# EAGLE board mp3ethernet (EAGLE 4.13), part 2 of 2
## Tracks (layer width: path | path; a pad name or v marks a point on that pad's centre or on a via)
+3V3  (via drill 0.5, 0.6)
  Top 0.254: 44.02,20 v43.97,19.94 v43.96,19.94 43.84,19.83 40.2,19.83 39.92,19.91 C73.1 | 43.2,60.31 | 43.2,60.31 43.27,60.29 43.83,60.84 v45.42,60.83 | R30.2 15.19,2.84 | L5.2 22.22,2.94 22.18,2.9 | 26.39,14.46 v26.39,14.62 26.39,14.47 26.65,14.22 | 25.24,4.88 25.25,4.87 25.25,4.86 | IC5.23 14.84,48.72 14.82,48.74 14.82,49.28 14.31,49.53 IC5.21 13.34,49.52 12.81,48.99 12.81,48.33 | 12.81,48.33 12.81,48.14 12.2,47.53 12.2,46.86 12.17,46.83 C25.2 | 47.49,28.3 47.5,28.31 | v48.43,28.01 48.42,28.01 48.44,28.03 48.47,28.02 | C15.1 24.51,39.74 v23.1,38.33 | 21.68,31.06 21.56,31.18 21.56,31.19 CON1.4 21.56,30.9 21.57,30.9 21.02,31.45 v20.46,31.45 | C13.1 21.68,23.9 | C27.1 13.31,56.47 13.3,56.46 14.1,55.66 14.49,55.66 14.84,55.31 IC5.13 14.84,54.6 13.94,54.6 v13.92,54.59 | IC1.71 57.97,44.8 v58.12,44.96 58.39,45.23 63.92,45.23 C61.2 | IC1.48 48.13,35.76 47.64,35.27 47.64,33.91 | v13.33,48.33 12.81,48.33 | 42.8,47.31 42.79,47.31 IC1.25 | IC8.5 33.06,35.79 32.82,35.55 29.96,35.55 29.51,36.01 | 21.2,33.97 C24.1 | 21.2,33.97 21.2,31.92 22.01,31.11 22.01,31.1 | 29.51,36.01 29.56,36.06 29.58,36.06 C67.1 | 24.95,39.74 24.95,38.19 25.96,37.18 28.3,37.18 28.31,37.19 | 28.31,37.19 28.31,37.2 | 21.2,33.97 21.2,33.11 21.62,32.7 22.62,32.7 v22.75,32.82 | 40.38,29.73 43.69,29.72 v44.03,29.38 | 40.38,29.73 v36.27,29.74 | 29.51,36.01 29.49,36.01 28.31,37.19 | 47.64,33.91 v45.91,33.91 | 47.64,33.91 47.57,33.84 47.44,33.84 | 40.38,29.73 40.38,29.67 40.3,29.59 C35.1
  Top 0.305: IC1.24 42.79,47.8 | IC1.24 42.78,47.38 42.75,47.35 42.78,47.32 IC1.25 44.96,47.3 45.84,46.44 45.85,43.8 | IC1.23 IC1.24 | 45.85,43.8 IC1.32 | 15.19,2.84 16.15,1.85 21.82,1.85 22.18,2.18 22.18,2.9 | L5.2 23.16,2.99 24.81,4.58 24.97,4.58 25.25,4.86 | 26.39,14.46 26.89,13.96 26.89,5.61 26.14,4.88 25.24,4.88 | v36.19,16.36 31.89,16.36 29.75,14.22 26.65,14.22 | 21.68,31.06 C13.1 | CON1.4 21.57,31.29 21.76,31.1 22.01,31.1 v22.6,31.1 | C24.1 21.29,32.05 21.63,31.7 | 56.01,44.8 IC1.71 54.18,44.8 50.87,48.06 50.53,48.4 | 46.07,44.18 46.1,44.05 45.85,43.8 | 45.85,43.8 44.95,43.8 | 47.45,28.26 47.44,33.84 47.44,33.88 | 47.45,28.26 47.48,28.24 | 47.45,28.26 47.45,28.07 47.48,28.05 48.39,28.05 v48.43,28.01 | 47.45,28.26 47.45,22.24 45.1,19.93 44.12,19.93 44.05,20.01 43.98,19.94 v43.97,19.94 | 47.49,28.3 47.49,28.19 47.48,28.17 47.45,28.2 47.45,28.26 | v38.07,47.11 38.27,47.31 39.17,47.31 39.49,47.63 41.13,47.63 41.44,47.31 42.79,47.31 | C59.+ 22.06,44.6 21.96,44.7 21.96,48.35 v21.95,48.37 | 50.53,48.4 50.52,48.41 | 50.53,48.4 | v45.91,33.91 v45.93,33.91 46.14,33.7
  Top 0.406: C15.1 24.95,39.74 24.96,39.76 23.73,40.99 C59.+ | v51.84,48.98 51.11,48.98 50.53,48.4 48.96,46.83 48.96,44.2 v48.73,43.97 v48.73,43.99 48.54,44.18 46.07,44.18 | 25.12,4.82 25.09,4.78 | 25.12,4.82 v25.12,4.87 | 25.24,4.88 25.19,4.88 25.12,4.82
  Top 0.61: SV3.2 46.15,55.49 46.14,55.49 46.14,55.91 44.16,57.9 44.16,59.35 43.2,60.31 41.43,62.08 41.43,64 | 41.43,64 41.43,64.05 41.41,64.03 L3.P$2 38.96,64.03 38.98,64.01 39.71,64.75 | 41.43,64 41.42,64 42.18,63.24 v42.18,63.21
  Bottom 0.254: 38.28,17.62 U1.28 38.24,17.59 38.23,17.58 38.23,17.59 38.23,18.07 38.24,18.09 | U1.20 43.44,17.61 | U1.20 | 43.44,17.66 U1.20 | U1.20 43.42,17.62 | U1.20 U1.19 | 46.69,16.98 U1.15 | 43.44,17.66 U1.20 | 43.44,17.66 43.44,16.53 43.98,15.97 46.04,15.97 46.67,16.59 46.69,16.98 | 46.69,16.98 46.69,16.99 | 46.68,16.98 46.68,16.99 | 46.69,16.98 46.68,16.98 | 46.68,16.98 46.87,16.79 49.7,16.79 49.79,16.81 50.1,16.5 50.1,16.47 50.09,16.46 52.71,14.2 L6.2 52.95,14.2 | C12.1 53.77,12.24 53.96,13.03 53.96,13.2 52.95,14.2 | 43.44,19.44 43.42,19.42 | 43.96,19.93 v43.97,19.94 | v45.42,60.83 v45.43,60.82 47.12,60.81 48.67,62.36 R3.2 | R41.2 | 26.41,5.57 26.47,5.57 R41.2 | R43.2 26.48,11.08 26.53,11.13 26.38,11.28 C52.2 26.38,14.61 v26.39,14.62 | v25.12,4.87 25.12,4.91 25.14,4.92 25.09,4.97 | IC2.14 19.53,36.07 19.51,36.05 19.49,36.07 IC2.13 19.48,37.31 18.57,38.22 C56.1 | v48.43,28.01 48.42,28.01 48.4,28.02 47.29,28.02 R11.2 47.16,27.85 47.17,27.84 47.2,27.87 47.2,28.5 46.32,29.38 v44.03,29.38 | v36.19,16.36 36.15,16.39 | 61.69,41.65 61.7,41.64 | 61.69,41.65 R40.2 62.63,41.65 62.96,41.32 62.97,37.86 62.56,37.46 62.56,37.17 62.55,37.15 IC10.8 | 61.69,41.65 61.66,41.67 R39.2 59.33,41.76 59.34,41.78 58.13,42.98 v58.12,44.96 | IC2.19 22.48,37.71 v23.1,38.33 | C42.1 15.71,31.86 15.7,31.87 15.71,31.88 | 15.71,32.03 15.69,32.05 15.77,32.13 | 15.77,32.13 15.86,32.22 | 15.65,31.72 15.69,31.76 15.69,31.91 15.78,32 C42.1 | 49.13,36.35 49.14,40.26 48.99,40.42 | v21.95,48.37 21.95,48.67 | 15.77,32.13 15.78,32.12 C42.1 | 15.77,32.13 | 15.65,31.72 13.67,31.72 | 13.67,31.72 12.47,31.72 11.99,31.23 R16.1 10.19,31.23 8.79,32.64
  Bottom 0.254: 46.17,52.75 46.18,52.74 | 46.17,52.75 R31.2 | 46.15,53.22 46.15,52.77 46.17,52.75 | 13.67,31.72 13.67,31.82 13.71,31.86 C71.1 | IC3.5 34.7,63.87 35,64.18 | 52.95,14.2 52.89,14.27 | IC2.45 20.98,29.21 20.97,29.22 21.97,29.22 | 21.97,29.22 24.49,29.22 24.48,29.2 IC2.38 24.48,26.31 25.25,25.53 C69.1 | IC2.43 21.98,29.21 21.97,29.22 | 18.14,31.72 15.65,31.72 | 18.14,31.72 IC2.6 | 21.97,29.22 22.04,29.22 22.04,31.1 v22.6,31.1 22.61,31.1 | 18.14,31.72 20.2,31.72 v20.46,31.45 | 21.29,34.04 21.29,33.6 22.06,32.82 v22.75,32.82 | 8.09,33.31 IC6.1 | 8.09,33.31 8.13,33.31 8.47,33.65 8.47,35.01 8.31,35.17 7.36,35.17 7.32,35.21 IC6.3 | 8.09,33.31 8.09,33.33 8.79,32.64 | 8.79,32.64 | C60.1 7.93,31.78 8.79,32.64 | R20.2 35.11,31.01 v36.27,29.74 | 13.92,52.32 C43.1 | 48.99,42.18 C70.1 | IC11.1 6.3,36.96 6.32,36.98 7.24,36.05 IC6.3 | IC6.3 7.21,35.21 6.85,35.57 C75.2 | 32.06,47.92 32.06,47.9 | U1.25
  Bottom 0.305: 38.28,17.62 38.28,19.44 40.19,19.44 | 40.19,19.44 U1.25 | 40.19,19.44 43.44,19.44 | 43.44,19.44 43.44,17.66 | 43.44,19.44 43.96,19.93 | v25.12,4.87 25.9,4.86 26.41,5.57 | IC12.8 20.8,7.06 21.07,7.33 22.8,7.32 23.68,7.32 25.09,5.94 25.09,4.97 | 38.24,18.09 C14.1 36.15,16.39 | 13.92,49.42 13.92,48.93 v13.33,48.33 | 13.92,49.42 13.92,52.32 v13.92,54.59 | IC2.14 19.98,35.09 21.02,34.04 21.29,34.04 22.48,34.04 22.48,34.02 22.47,34.02 22.48,34.02 IC2.19 | v22.6,31.1 22.44,31.25 | 48.14,45.24 48.18,45.29 C62.2 | 48.99,40.42 48.99,42.18 | v45.91,33.91 47.2,33.91 47.69,34.42 47.69,34.65 49.13,36.09 49.13,36.35 | v38.07,47.11 37.99,47.08 | 23.68,48.37 24.12,48.37 24.57,47.92 32.06,47.92 32.07,47.92 32.39,48.24 36.49,48.24 R32.2 | 23.68,48.37 v21.95,48.37 | R32.2 36.9,47.83 | R32.2 | 23.68,48.37 C63.1 | 21.95,48.67 20.39,50.23 18.98,50.23 18.16,49.42 13.92,49.42 | R48.2 32.32,47.63 32.06,47.9
  Bottom 0.406: SV3.2 46.15,53.22 46.83,52.75 49.83,49.74 50.73,48.9 50.74,48.9 50.82,48.98 v51.84,48.98 | C62.2 48.24,45.31 48.73,44.81 v48.73,43.97 48.71,43.97 48.72,43.96 48.72,42.42 48.96,42.18 48.99,42.18
  Bottom 0.61: C30.+ v42.18,63.21 42.19,63.21 40.75,64.66 36.99,64.66 36.5,64.18 35,64.18 | 37.99,47.08 36.97,47.08 | R33.2 36.92,46.42 36.97,46.47 36.97,47.08 | R32.2 36.91,47.85 36.97,47.78 36.97,47.08
+5V  (via drill 0.5, 0.6)
  Top 0.254: SV2.19 63.16,68.22 63.16,64.38 C66.1 | LED1.A 69.3,67.4 69.7,67.8 73.18,67.8 | 73.18,67.8 73.19,67.8 | v73.6,67.01 73.6,67.38 73.18,67.8 | 19.21,61.22 19.21,60.84 20.48,59.57 C74.1
  Top 0.305: R28.2 24.9,60.37 v22.71,60.37
  Top 0.406: SV2.17 SV2.19 63.17,68.27 63.21,68.31 63.81,68.31 65.87,70.36 65.89,70.39
  Top 0.61: 65.74,72.08 65.66,72.15 65.66,72.23 65.15,72.74 41.14,72.76 40.25,71.86 SV2.2 | LED1.A 69.3,67.36 69.3,67.25 69.21,67.16 65.87,70.36 65.78,70.45 65.78,72.04 65.74,72.08 | 65.74,72.08 v65.76,72.05 | v22.71,60.37 22.71,60.39 22.72,60.41 21.91,61.22 21.03,61.22 19.21,61.22 17.94,61.22
  Top 0.813: 19.21,61.22 19.21,61.24 | 21.03,61.22 21.03,61.12 21.01,61.14 v21.01,61.16
  Top 1.016: 17.94,61.22 17.94,62.99
  Top 1.27: 17.94,62.99 L2.P$1
  Bottom 0.254: IC3.8 36.8,62.87 35.8,61.85 34.46,61.85 34.44,61.87 | 34.44,61.87 IC3.1 | 34.44,61.87 32.91,60.41 31.94,59.44 C31.1 31.94,60.14 31.78,60.31 | 69.69,5.11 C64.1 | IC13.VCC 69.72,5.08 69.69,5.11 | 69.69,5.11 69.69,8.15 | 69.69,8.15 69.69,9.45 70.15,9.91 70.15,59.2 68.44,60.9 68.01,60.9 61.05,67.82 61.05,68.22 61.09,68.26 60.58,68.26 SV2.17 | C65.1 70.29,8.15 69.69,8.15 | C68.1 25.48,58.49 25.48,59.28 | IC4.5 73.76,66.85 v73.6,67.01
  Bottom 0.305: v22.71,60.37 22.69,60.34
  Bottom 0.61: 37.34,69.11 32.54,64.32 31.77,64.32 31.78,59.67 31.94,59.51 C31.1 | 37.34,69.11 39.03,70.81 39.26,70.81 | 22.71,60.34 22.71,60.29 | 31.78,60.31 31.78,59.39 31.89,59.28 25.48,59.28 23.52,59.29 | SV2.2 39.26,70.81 | 39.26,70.81 | 37.34,69.11 | C72.1 37.34,69.11
  Bottom 0.813: C33.+ 20.86,61.31 v21.01,61.16 | 23.52,59.29 23.52,59.33 23.04,59.81 23.04,60.01 22.71,60.34 v22.71,60.37
  Bottom 1.016: 31.78,60.31 31.78,59.67 31.78,59.35 31.93,59.2
AUX_L
  Top 0.254: JP4.3 26.31,46.61 26.29,46.6 25.96,46.93 C57.2
AUX_R
  Top 0.254: C58.2 24.35,49.78 24.9,49.23 26.47,49.23 26.53,49.17 26.52,49.15 JP4.2
CDSD
  Top 0.254: CON1.10 9.9,29.25 11.17,27.98 14.71,27.98 21.01,21.68 38.89,21.68 38.92,19.11 45.3,19.11 48.54,22.33 48.54,23.42 50.02,24.9 50.02,30.82 49.83,31.01 49.83,33.34 49.84,33.46 50.88,34.69 51.31,35.1 51.32,35.91 50.64,36.54 50.64,37.75 50.63,37.76 IC1.53
CS0  (via drill 0.6)
  Top 0.254: SV1.37 71.33,56.46 70.26,57.51 68.11,57.51 67.87,57.27 62.63,57.27 62.23,57.27 62.52,57.26 v62.1,57.26 | IC1.72 54.58,45.3 54.2,45.68 v54.2,46.2
  Bottom 0.254: v62.1,57.26 62.11,57.12 61.3,56.31 60.56,56.31 60.26,56.01 60.26,54.61 59.91,54.26 57.71,52.1 57.53,51.91 56.48,50.85 56.49,47.55 | 56.49,47.55 | v54.2,46.2 55.13,46.2 56.49,47.55
CS1  (via drill 0.6)
  Top 0.254: SV1.38 68.77,56.45 68.63,56.3 62.13,56.3 61.33,55.5 v61.09,55.49 | v54.3,43.93 54.3,43.82 54.53,43.8 IC1.69
  Bottom 0.254: v61.09,55.49 61.09,55.36 61.1,54.91 61.09,54.8 57.02,50.72 57.02,46.88 57.03,46.87 54.33,44.25 54.3,44.22 v54.3,43.93
CSENC  (via drill 0.6)
  Top 0.254: IC1.43 45.63,36.8 43.7,36.81 43.54,36.63 43.53,35.92 43.53,34.88 43.51,31.64 44.94,30.3 44.96,27.6 44.19,26.83 v43.42,26.83
  Bottom 0.254: U1.9 43.44,24.93 43.46,24.96 43.42,25 v43.42,26.83
CSSD
  Top 0.254: IC1.37 40.74,41.3 40.14,40.7 40.14,38.79 36.72,35.4 35.35,35.4 33.93,33.98 29.68,33.97 29.06,33.34 CON1.1
D+  (via drill 0.6)
  Top 0.254: X1.D+ 43.12,14.37 50.22,21.67 50.22,22.51 51.81,24.1 51.84,31.62 52.54,33.32 v52.54,33.65 | v47.22,47.95 47.23,48.79 47.23,49.03 46.65,49.61 46.65,51.03 46.63,51.05 IC1.16
  Bottom 0.254: v52.54,33.65 52.54,35.41 51.97,36.01 51.13,36.84 50.12,37.84 50.09,46.11 48.97,47.22 47.95,47.22 v47.22,47.95
D-  (via drill 0.6)
  Top 0.254: IC1.17 46.13,48.27 46.05,48.18 46.05,48.05 v46,48 | v41.93,10.46 41.93,14.03 41.98,14.08 41.98,14.09 49.72,21.85 49.72,22.78 51.35,24.39 51.37,31.78 51.71,32.61 v51.34,33.86 v51.32,33.86
  Bottom 0.254: v51.32,33.86 51.32,35.88 50.87,36.31 49.61,37.55 49.62,45.93 49.61,45.93 48.94,46.6 47.23,46.6 46.7,47.12 46,47.81 v46,48 | v41.93,10.46 41.86,10.39 40.91,10.39 40.38,9.87 40.39,8.32 40.97,7.74 42.15,7.74 42.23,7.66 42.27,7.7 X1.D-
DA0  (via drill 0.6)
  Top 0.254: SV1.35 71.33,53.96 70.08,55.21 68.26,55.21 63.5,55.2 62.92,55.2 v62.66,55.46 | 62.67,55.47 v62.66,55.46 | IC1.68 57.37,43.3 59.16,43.3 59.49,43.63 v59.67,43.63 | v62.66,55.46 62.65,55.47
  Bottom 0.254: v62.66,55.46 62.37,55.46 62.35,55.48 61.61,54.74 61.62,54.59 59.06,52.03 57.57,50.54 57.57,47.31 58,46.88 58,46.69 58,46.51 58.54,45.98 59.67,44.86 v59.67,43.63 | v62.67,55.46 v62.66,55.46 | 62.6,55.45 62.6,55.46 v62.66,55.46
DA1  (via drill 0.6)
  Top 0.254: IC1.66 61.86,42.3 62.25,42.69 62.25,43.38 62.26,43.39 | SV1.33 70.63,51.37 69.56,52.43 64.49,52.43 v63.5,53.41 | 62.26,43.39 | 62.26,43.39 v62.26,43.3
  Bottom 0.254: v63.5,53.41 63.4,53.41 62.55,53.37 61.92,53.36 60.85,52.3 60.56,52 58.72,50.15 58.68,50.11 58.68,48.01 59.18,47.51 59.18,47.02 62.26,43.93 62.26,43.55 62.27,43.54 62.26,43.53 v62.26,43.3 | 63.48,53.43 v63.5,53.41 | v63.49,53.41 v63.5,53.41
DA2  (via drill 0.6)
  Top 0.254: SV1.36 68.58,53.91 68.31,54.2 63.45,54.2 62.4,54.2 v62.35,54.21 | IC1.67 58.26,42.8 60.61,42.79 60.99,43.17 v60.99,43.88
  Bottom 0.254: v62.35,54.21 61.94,54.22 59.87,52.14 59.61,51.89 58.17,50.44 58.17,47.6 58.57,47.2 58.56,46.85 58.56,46.84 59.91,45.49 60.05,45.34 60.99,44.4 v60.99,43.88 | v62.35,54.21 62.33,54.21 62.32,54.22 62.33,54.23 | v62.35,54.21 62.36,54.21 62.37,54.2
DD0
  Top 0.254: IC1.62 56.97,40.29 57.62,39.64 57.62,39.15 58.6,38.14 65.17,38.14 68.41,34.91 69.33,34.91 70.11,34.13 70.11,32.29 71.33,31.07 SV1.17
DD1
  Top 0.254: SV1.15 71.33,28.52 70.04,29.81 68.47,29.81 67.97,30.31 67.73,30.56 67.74,34.53 67.74,34.87 64.89,37.7 58.41,37.71 56.31,39.8 IC1.61 55.99,39.81
DD2
  Top 0.254: SV1.13 71.34,25.95 | SV1.13 | SV1.13 70,27.29 68.24,27.29 67.19,28.34 67.19,30.37 67.17,34.3 67.17,34.63 64.57,37.2 58.04,37.2 56.85,38.41 54.54,38.41 54.13,38 IC1.60
DD3
  Top 0.254: 71.34,23.43 71.38,23.39 | 71.34,23.43 SV1.11 | 71.34,23.43 70.09,24.67 68.32,24.67 66.67,26.32 66.67,30.12 66.64,30.16 66.63,30.16 66.62,33.79 66.62,34.47 64.41,36.66 57.81,36.66 56.53,37.91 54.89,37.9 54.89,37.14 54.46,36.71 54.36,36.7 53.89,36.7 53.79,36.78 53.62,36.95 53.62,37.9 53.64,37.91 53.63,37.92 IC1.59
DD4  (via drill 0.5, 0.6)
  Top 0.254: SV1.9 71.33,20.91 70.02,22.22 67.94,22.22 66.13,24.03 66.13,29.91 66.14,33.26 66.14,34.26 64.25,36.1 57.29,36.1 56.37,37.03 v55.78,37.03 | IC1.39 43.73,40.3 44.11,40.71 44.11,42.36 44.75,42.98 44.94,43.16 46.68,43.16 50.69,43.16 v51.39,43.85
  Bottom 0.254: v51.39,43.85 51.51,43.85 51.51,43.76 51.54,43.73 51.96,43.57 54.96,40.56 54.96,37.9 55.79,37.04 v55.78,37.03
DD5  (via drill 0.5)
  Top 0.254: SV1.7 70.02,19.66 68.26,19.66 65.64,22.26 65.64,29.72 65.66,32.99 65.66,34.06 64.15,35.54 57.06,35.54 56.71,35.9 v56.29,35.88 | IC1.40 43.93,39.8 44.57,40.44 44.57,42.11 45.18,42.73 51.5,42.73 51.55,42.7 v51.68,42.69
  Bottom 0.254: v51.68,42.69 52.18,42.69 54.18,40.67 54.18,37.34 55.63,35.88 v56.29,35.88
DD6  (via drill 0.5)
  Top 0.254: SV1.5 71.35,15.78 | SV1.5 | SV1.5 69.99,17.14 67.91,17.14 65.13,19.92 65.13,33.84 64,34.96 57.43,34.96 57.2,34.73 v56.66,34.73 | IC1.41 44.63,39.73 44.63,39.86 45.05,40.28 45.06,41.74 45.52,42.19 50.42,42.19 51.21,41.6 v51.4,41.6
  Bottom 0.254: v51.4,41.6 51.49,41.6 51.68,41.75 52.39,41.76 53.7,40.45 53.7,39.96 53.69,37.15 55.86,34.96 56.09,34.73 v56.66,34.73
DD7  (via drill 0.5, 0.6)
  Top 0.254: SV1.3 71.33,13.38 70.08,14.63 68.01,14.63 64.51,18.13 64.51,33.71 63.88,34.33 58.77,34.35 58,34.35 v57.43,33.77 | IC1.42 45.13,39.7 45.67,40.24 45.67,41.51 45.83,41.65 49.77,41.66 51.17,40.8 v52.21,40.8
  Bottom 0.254: 57.43,33.84 v57.43,33.77 57.41,33.77 57.38,33.75 57.34,33.79 56.34,33.79 53.23,36.91 52.84,37.32 52.21,37.97 v52.21,40.8
DD8  (via drill 0.6)
  Top 0.254: v62.38,52.51 62.33,52.62 62.02,52.92 61.09,52.93 53.2,52.93 53.14,52.86 53.13,52.86 52.64,52.38 52.64,51.19 52.63,51.17 IC1.4
  Bottom 0.254: v62.38,52.51 62.62,52.76 | v62.38,52.51 62,52.51 61.99,52.52 59.36,49.91 59.36,49.9 59.22,49.76 59.22,48.39 59.73,47.88 59.73,47.11 63.08,43.79 63.54,43.34 63.54,42.33 63.57,19.15 SV1.4 | v62.38,52.51 62.39,52.51 62.58,52.41 64.1,52.41 64.38,52.69 64.38,59.16 59.74,63.73 54.87,63.73 SV2.9
DD9  (via drill 0.6)
  Top 0.254: v63.31,51.35 63.24,51.35 63.1,51.5 61.9,51.51 60.95,52.48 57.35,52.48 54.88,52.48 53.38,52.48 53.13,52.23 53.13,51.17 53.14,51.16 IC1.3
  Bottom 0.254: SV1.6 68.83,15.81 64.09,20.74 64.11,43.7 60.39,47.23 60.38,48.11 59.86,48.62 59.86,49.5 60.46,50.1 62.77,50.1 63.48,50.83 63.49,51.35 v63.31,51.35 v63.3,51.35 63.4,51.25 63.94,51.25 64.85,52.16 64.85,59.37 59.95,64.24 55.4,64.24 51.87,67.8 51.87,69.33 50.41,70.79 SV2.10
DD10  (via drill 0.6)
  Top 0.254: IC1.78 60.19,48.3 v60.84,48.94
  Bottom 0.254: SV1.8 68.81,18.32 | SV1.8 | SV1.8 64.62,22.66 64.63,43.89 61.03,47.36 61.03,48.82 60.91,48.94 v60.84,48.94 61.22,49.52 62.88,49.52 63.57,50.22 63.61,50.26 63.58,50.23 65.31,51.96 65.31,59.57 60.09,64.74 56.46,64.74 52.97,68.27 SV2.11
DD11  (via drill 0.6)
  Top 0.254: IC1.77 61.33,47.8 v62.11,48.57
  Bottom 0.254: SV1.10 65.2,24.65 65.2,44.08 62.11,47 v62.11,48.57 62.46,48.92 63.31,48.92 64.24,49.85 65.76,51.38 65.76,59.76 60.29,65.19 56.95,65.19 54.21,67.98 54.21,69.6 52.98,70.83 SV2.12 | SV2.12
DD12  (via drill 0.6)
  Top 0.254: IC1.76 62.71,47.3 v63.35,47.94
  Bottom 0.254: 68.79,23.39 68.8,23.39 | 68.79,23.39 SV1.12 | 68.79,23.39 65.68,26.51 65.69,44.24 63.37,46.56 v63.35,47.94 v63.36,47.94 66.22,50.81 66.22,59.96 60.46,65.73 58,65.73 SV2.13 | SV2.13
DD13  (via drill 0.6)
  Top 0.254: IC1.75 64.04,46.79 v64.56,47.31
  Bottom 0.254: SV1.14 66.35,28.4 66.35,44.3 64.56,46.08 v64.56,47.31 65.59,48.34 | 65.59,48.34 | 65.59,48.34 65.64,48.34 66.68,49.38 66.68,60.15 60.67,66.19 58.64,66.19 56.87,67.95 56.87,69.42 SV2.14 | SV2.14
DD14  (via drill 0.6)
  Top 0.254: IC1.74 65.39,46.3 v65.73,46.64
  Bottom 0.254: 68.79,28.49 68.81,28.48 | SV1.16 68.79,28.49 | 68.79,28.49 67.01,30.28 67.01,44.38 66.4,44.99 65.73,45.65 v65.73,46.64 65.75,46.64 66.19,47.08 66.19,47.07 66.22,47.07 67.26,48.11 67.26,59.64 67.29,59.67 67.29,60.22 60.85,66.67 59.69,66.67 58.07,68.28 58.06,68.27 SV2.15
DD15  (via drill 0.6)
  Top 0.254: IC1.73 v66.81,45.8 v66.82,45.8
  Bottom 0.254: SV1.18 68.8,31.05 67.58,32.28 67.58,45.24 67.01,45.8 v66.82,45.8 66.84,45.83 66.86,45.83 66.86,46.17 67.76,47.07 67.76,60.43 61.09,67.12 60.09,67.12 59.29,67.9 59.29,69.59 58.07,70.81 SV2.16
DIOR
  Top 0.254: SV1.25 71.33,42.2 70.34,43.2 70.34,45.24 70.04,45.53 70.04,46.67 69.28,47.43 67.39,47.43 64.93,49.89 62.12,49.89 61.81,50.2 60.13,50.2 59.2,49.28 56.06,49.28 56.04,49.31 56.03,49.3 IC1.80
DIOW
  Top 0.254: SV1.23 71.33,38.64 71.31,38.63 71.26,38.68 70.16,38.68 69.89,38.94 69.89,44.51 69.36,45.04 68.48,45.04 67.72,45.78 67.71,46.21 64.44,49.47 61.89,49.47 61.59,49.75 60.37,49.75 60.23,49.61 59.44,48.81 59.15,48.8 IC1.79
DREQ  (via drill 0.5)
  Top 0.254: v19.76,33.99 19.76,34.68 20.06,34.98 22.33,34.98 22.5,34.82 22.5,33.98 22.89,33.58 23.73,33.58 24.64,34.5 33.79,34.52 34.6,35.34 34.6,38.83 34.14,39.29 34.14,42.66 34.4,42.92 35.96,42.91 36.08,43.05 39.5,43.05 39.73,42.8 IC1.34
  Bottom 0.254: IC2.8 19.65,32.72 19.76,32.84 v19.76,33.99
GND  (via drill 0.5, 0.8)
  Top 0.254: 58.98,44.3 59,44.32 | C28.2 21.8,12.2 21.68,12.08 21.68,11.54 21.26,11 20.49,11 20.49,8.93 20.48,8.93 | S3.2 54.48,63.66 54.49,63.66 54.28,63.45 S3.GND | IC9.17 20.48,8.93 | 20.48,8.93 | IC9.4 IC9.5 15.54,7.4 15.52,7.38 15.54,7.37 IC9.6 | IC9.3 15.51,8.43 15.51,7.93 IC9.4 | IC9.24 16.27,10.18 16.27,9.42 | 16.27,9.42 16.27,9.39 16.34,9.39 IC9.GNDPAD 17.16,8.2 16.91,7.94 15.5,7.94 15.48,7.93 | 16.27,9.42 16.26,9.42 16.25,9.43 IC9.1 15.54,9.44 15.56,9.47 15.54,9.49 15.54,9.98 14.82,10.69 L4.2 | 15.48,7.93 15.47,7.92 | IC9.4 15.48,7.93 | D3.2 D3.3 | IC9.14 20.14,7.43 20.43,7.14 20.43,6.37 20.65,6.14 21.96,6.14 22.18,5.92 22.18,4.89 22.14,4.86 22.19,4.81 C23.2 | IC5.20 12.78,50.01 12.53,49.75 12.53,49.48 12.2,49.17 12.2,48.27 11.94,48.01 10.9,48.01 10.15,47.26 10.17,47.25 C25.1 | S1.2 63.29,32.09 61.35,32.09 | 61.35,32.09 S1.GND | JP3.1 61.84,27.4 61.35,27.89 61.35,32.09 | v22.61,26 22.6,25.99 23.68,24.91 C13.2 | v17,27.77 16.62,28.12 16.56,28.18 CON1.6 | 59,44.32 59.46,44.77 62.28,44.77 64.21,42.85 | 64.21,42.85 C61.1 | SV1.28 67.9,42.85 64.21,42.85 | v49.6,34.63 49.44,34.5 49.33,34.64 49.33,34.42 49.64,35.29 IC1.51 | JP5.1 34.31,44.39 34.25,44.3 IC1.31 44.01,44.3 | IC1.26 44.24,46.8 44.24,44.3 44.01,44.3 | IC5.3 19.13,50.52 19.12,51.54 | IC5.5 18.25,51.52 18.28,51.54 19.12,51.54 | IC5.10 16.34,59.03 15.94,59.43 13.48,59.43 13.29,59.24 13.29,58.54 13.25,58.5 13.27,58.49 C27.2 | IC5.24 15.34,47.88 14.57,47.08 v13.81,46.87 | 26.37,51.73 JP4.1 26.1,51.47 | v20.69,51.52 20.65,51.52 20.64,51.5 20.6,51.54 19.12,51.54 | 44.01,44.3 44.01,44.33 44.81,45.13 v44.64,45.42 | IC1.11 49.13,50.07 49.42,49.78
  Top 0.254: IC1.70 57.18,44.3 57.52,43.96 58.63,43.96 58.99,44.33 59,44.32 | 59,44.32
  Top 0.305: CON1.3 24.06,30.81 24.07,30.8 23.23,30.02 v22.89,30.03
  Top 0.61: IC7.6 35.73,63.12 | 36.32,62.93 37.07,62.17 37.21,62.31 | D3.2 7.73,13.14 X3.3
  Bottom 0.254: 44.75,24.83 44.74,24.84 U1.11 | IC3.2 IC3.3 33.48,62.87 33.47,62.88 35.87,62.88 36.38,63.39 38.38,63.39 38.39,63.39 IC3.7 | IC3.7 38.39,63.42 38.38,63.43 38.39,63.44 IC3.6 | 68.84,43.75 68.86,43.72 | SV1.28 68.84,43.75 | SV1.30 68.79,43.79 68.84,43.75 | SV1.22 SV1.24 | SV1.24 68.79,38.71 68.74,38.77 | 68.76,41.21 68.75,41.22 | 68.76,41.21 SV1.26 | SV1.24 68.79,41.17 68.76,41.21 | SV1.40 | v22.61,26 22.42,25.96 22.98,26.52 IC2.41 | 20.56,38.22 20.53,38.26 | 20.56,38.22 C56.2 | IC2.16 20.98,37.81 20.56,38.22 | IC2.22 23.98,37.14 24.04,37.2 | v17,27.77 16.6,28.11 18.14,26.57 19.88,26.57 19.98,26.67 IC2.47 19.96,27.89 19.96,29.15 19.92,29.19 19.92,30.04 | v13.81,46.87 13.8,46.34 13.78,46.32 | IC2.35 29.81,29.72 30.01,29.51 31.89,29.51 32.16,29.24 32.16,28.39 32.17,28.38 32.15,28.35 R13.2 | 16.69,30.72 IC2.4 | 16.69,30.72 16.69,30.71 | v22.89,30.03 22.97,30 22.94,30.03 | 16.69,30.72 19.27,30.72 | 19.92,30.04 19.92,30.07 | U1.18 44.74,19.24 45.48,19.98 45.48,20.25 44.64,21.09 43.41,21.09 42.31,19.98 | IC3.10 39.47,61.87 39.68,62.08 39.68,63.16 39.45,63.39 38.43,63.39 38.41,63.37 38.4,63.37 IC3.7 | 19.92,30.04 19.87,30.04 19.19,30.72 16.69,30.72 | 34.43,63.37 33.05,63.37
  other vias: 24.97,10.69 49.11,63.75 36.72,60.33 53.23,47.64 40.14,32.35 41.32,31.68 70.2,60.5 67.85,73.2 68.05,70.13 73.59,68.8 73.04,55.26 73.04,52.68 73.02,50.13 73.02,47.58 55.2,33.18 59.33,20.13 61.83,17.58 36.2,19.64 53.42,27.81 44.63,14.43 56.61,25.75 46.05,10.6 58.17,13.33 61.67,15.23 66.5,10.88 66.08,5.12 62.45,2.61 55.38,2.71 42.68,2.8 36.22,4.93 32.1,2.18 34.1,9.94 36.07,14.78 34.12,20.38 8.25,59.06 3.04,58.86 2.98,48.98 1.77,35.62 2.52,31.06 2.39,25.41 2.45,20.29 2.51,14.93 7.56,14.79 13.75,15.78 19.21,19.8 24.34,19.78 19.07,15.16 25.7,23.84 30.31,23.82 30.56,26.87 37.46,31.12 37.13,24.31 34.62,24.34 37.93,34.31 40.1,36.45 31.7,36.66 30.62,42 18.49,36.19 18.66,39.98 7.65,28.28 11.98,26.83 7.76,67.05 14.81,67.23 19.64,67.23 29.91,70.71 39.4,73.36 49.76,57.5 47.44,57.52 42.05,53.23 37.21,53.41 10.23,8.32 8.53,8.32 10.27,6.43 10.27,4.45 11.03,2.75 16.65,2.79 23.08,15.93 20.54,17.16 73.33,42.5 73.33,34.96 73.28,29.56 73.19,24.53 73.28,19.6 73.28,14.57 73.26,9.68 73.35,6.05 71.39,5.9 68.83,8.04 56.76,9.63 52.91,2.82 10.6,56.63 12.73,54.7 73.63,59.12 17.71,8.21 32.08,52.85 44.78,49.14 11.46,59.97 22.15,59.06 23.84,57.83 19.38,44.09 25.04,44.1 27.11,44.12 34.73,29.34 30.33,19.78 29.68,15.85 30.7,12.91 33.42,3.65 33.91,5.29 33.99,6.65 36.14,10.74 28.05,15.82 26.47,16.02 24.6,16.07 24.68,1.69 10.98,14.79 12.49,12.4 8.51,46.72 26.27,27.56 72.77,66.06 8.3,40.35 14.23,39.03 37.04,37.76 13.26,72.46 21.47,72.48 32.46,39.57 60.42,59.43 64.39,66.82
  pour Top (isolate 0.305): -0.65,74.52 75.6,74.58 75.74,0.11 -0.48,0.19
  pour Bottom: -0.34,74.76 75.01,74.72 75.01,0.25 -0.47,0.27
I2C_SCL  (via drill 0.5)
  Top 0.254: IC9.9 17.29,5.28 15.97,5.28 15.37,4.68 v15.27,4.56 | IC1.64 54.29,41.3 54.28,42.44 53.84,42.44 52.14,44.15 52.14,44.7 52.15,44.71 51.5,45.29 51.5,45.93 51.53,45.99 51.53,46.13 v51.5,46.13 | v14.81,16.82 9.85,16.82 3.66,23.01 3.69,32.34 3.69,34.3 4.65,35.26 7.9,38.45 9.49,39.96 v9.49,43.53 9.5,43.52 | IC5.12 15.34,55.88 v14.85,56.37 | v22.13,52.24 22.6,52.25 23.82,53.49 v23.82,53.71
  Bottom 0.254: v15.27,4.56 15.27,12.07 15.65,12.46 15.65,13.4 14.8,14.25 v14.81,16.82 | R40.1 61.64,39.73 60.05,38.13 IC10.6 60.01,36.16 59.49,35.64 58.25,35.64 58.09,35.79 58.09,38.51 54.6,41.99 54.22,42.06 52.15,44.14 52.15,44.7 51.5,45.27 v51.5,46.13 | v14.85,56.37 12.41,56.39 12.22,56.39 9.36,53.54 9.33,46.7 9.33,45.64 9.25,45.53 9.25,44.44 9.49,44.19 v9.49,43.53 9.49,39.77 9.86,39.4 10.82,39.4 10.98,39.56 IC11.12 | 51.51,46.18 51.08,46.61 51.08,46.92 47.35,50.64 41.79,50.62 41.04,51.43 39.06,51.42 38.26,50.6 32.06,50.6 31.84,50.4 24.65,50.4 22.84,52.24 v22.13,52.24 | v23.82,53.71 22.48,55.05 19.02,55.05 17.69,56.37 v14.85,56.37 | v14.85,56.37 v14.84,56.37
  Bottom 0.305: v51.5,46.13 51.5,46.11 51.51,46.12 51.51,46.18
I2C_SDA  (via drill 0.5)
  Top 0.254: v16.23,3.97 16.23,4.35 16.56,4.68 17.48,4.68 17.79,4.99 IC9.10 | IC1.65 55.03,41.8 54.79,41.8 54.79,42.94 54.04,42.94 53.1,43.87 53.1,44.75 v53,44.75 | v15.76,17.6 9.85,17.62 4.23,23.23 4.26,32.03 4.26,33.91 10.38,40.04 10.38,40.05 10.48,40.15 v10.48,40.19 | IC5.7 18.23,54.37 v18.05,54.55 | v10.37,45.2 10.35,45.19 | v37.39,51.77 37.21,51.77 35.73,53.26 34.51,53.26 v34.01,53.75
  Bottom 0.254: v16.23,3.97 16.23,4.21 16.22,4.82 16.22,4.95 15.76,5.4 15.76,11.82 16.16,12.21 16.16,14.51 15.42,15.26 15.42,16.27 15.74,16.59 15.75,17.58 v15.76,17.6 | IC10.5 58.74,37.17 58.72,37.19 58.73,37.2 58.74,38.12 59.33,38.7 R39.1 58.19,39.99 55.19,42.98 54.02,42.98 53.03,43.96 53.03,44.44 53.01,44.76 | 53.01,44.76 v53,44.75 | 10.37,45.23 10.37,45.22 | 10.37,45.23 10.37,45.24 9.88,45.74 9.88,46.45 9.93,53.24 12.16,55.49 17.09,55.49 v18.05,54.55 v18.04,54.56 21.49,54.56 23.66,52.39 23.94,52.39 25.3,53.75 v34.01,53.75 | 53.01,44.76 53,45.85 51.68,47.15 51.67,47.11 47.49,51.26 41.96,51.26 41.25,51.97 38.74,51.96 37.58,51.96 v37.39,51.77 | 10.5,40.21 IC11.11 | v10.48,40.19 10.5,40.21 | 10.37,45.23 v10.37,45.2 | 10.5,40.21 10.5,45.09 10.37,45.23
INTRQ
  Top 0.254: IC1.1 54.13,50.53 54.72,49.94 58.92,49.94 59.66,50.68 62.14,50.68 62.39,50.44 67.2,50.44 67.59,50.04 70.18,50.04 71.34,48.89 71.33,48.88 SV1.31
IR
  Top 0.254: IC13.OUT 64.72,12.73 65.87,13.87 65.87,15.63 62.02,19.47 62.02,24.8 60.51,26.31 60.51,28.68 59.62,29.57 54.41,29.57 53.97,30 53.98,34.7 51.63,37.02 IC1.55
LCDCD
  Top 0.254: SV2.7 47.88,68.27 51.63,64.52 IC1.6
LCDCS  (via drill 0.6)
  Top 0.254: v53.84,49.05 53.84,49.6 53.62,49.81 53.62,51.05 53.64,51.06 53.63,51.06 IC1.2 | SV2.6 45.67,70.81 | v57.03,59.3 56.73,59.3 56.72,59.31 56.72,61.47 56.94,61.69 56.95,68.89 56.33,69.53 49.71,69.53 49.14,70.1 49.14,71.7 48.85,71.99 46.51,71.99 SV2.6 | SV2.6 | SV2.6
  Bottom 0.254: v57.03,59.3 56.73,59.3 56.72,51.94 v53.84,49.05
LCDPWM  (via drill 0.6)
  Top 0.254: 62.83,57.92 67.72,57.92 67.75,57.94 70.67,57.94 70.89,57.71 71.92,57.71 72.53,58.32 v72.53,60.57 | 52.1,51.18 IC1.5 52.13,52.53 53,53.4 59.08,53.4 59.11,53.42 | 62.83,57.92 62.82,57.92 | 62.83,57.92 62.63,58.12 61.78,58.12 61.26,57.6 61.04,57.37 60.21,56.55 60.21,54.53 59.11,53.42 | 59.11,53.42 59.1,53.41
  Bottom 0.254: v72.53,60.57 72.64,60.68 72.64,60.7 72.77,60.84 72.77,62.15 72.81,62.18 | 73.76,62.11 73.78,62.1 | 73.76,62.11 IC4.1 | 73.76,62.11 73.72,62.15 IC4.2 72.81,62.18 | 72.81,62.18 72.84,62.21
LCDRD
  Top 0.254: IC1.7 51.13,64.18 48.2,67.11 46.41,67.11 45.33,68.19 SV2.5
LCDWR
  Top 0.254: IC1.8 50.63,63.74 47.9,66.48 46.22,66.48 45.6,67.1 42.24,67.1 41.63,67.71 41.63,69.64 SV2.4
LEDA  (via drill 0.5)
  Top 0.254: v38.65,14.55 38.65,11.61 36.33,9.29 36.33,7.05 37.35,6.03 47.45,6.03 48.64,4.83 52.19,4.83 52.2,4.84
  Top 0.406: 52.2,4.84 v52.26,4.84
  Bottom 0.254: U1.27 38.89,14.78 v38.65,14.55 | 51.02,4.85 51.02,4.86 | 51.02,4.85 R5.1 | v52.26,4.84 51.03,4.84 51.02,4.85
LEDB  (via drill 0.5)
  Top 0.254: v39.78,14.51 39.78,12.03 36.8,9.05 36.8,7.3 37.46,6.63 47.86,6.63 48.86,5.63 52.62,5.63 53.39,4.86
  Top 0.406: v53.37,4.86 53.39,4.86 53.41,4.86 53.43,4.83
  Bottom 0.254: U1.26 39.54,14.75 v39.78,14.51 | 54.62,4.85 54.65,4.82 | 54.62,4.85 R6.1 | v53.37,4.86 54.61,4.86 54.62,4.85
MCLR  (via drill 0.6)
  Top 0.254: 47.13,59.25 47.25,59.25 48.68,57.82 48.68,55.35 48.69,55.35 SV3.1 48.69,55.23 48.68,55.23 48.68,54.58 50.13,53.13 50.13,51.29 50.12,51.28 50.13,51.26 IC1.9 | 47.13,59.25 47.04,59.25 | 47.04,59.25 S3.3 | 47.13,59.25 47.13,59.16 | v48.81,59.16 48.77,59.16 48.66,59.25 47.04,59.25
  Bottom 0.254: v48.81,59.16 48.81,60.55 48.87,60.61 48.82,60.66 R3.1
N$1  (via drill 0.5)
  Top 0.254: IC1.49 48.62,35.54 48.14,35.07 48.14,32.63 49.06,31.69 v49.09,31.66
  Bottom 0.254: v49.09,31.66 49.09,31.65 49.81,30.94 C2.2 | v49.09,31.66 | Q1.2 48.74,31.3 v49.09,31.66
N$2  (via drill 0.6)
  Top 0.254: IC1.50 49.13,37.91 49.15,37.89 49.1,37.84 49.1,35.34 48.71,34.94 48.71,33.17 48.85,33 v48.99,33
  Bottom 0.254: v48.99,33 49.22,32.77 49.19,32.68 50.13,31.79 50.46,31.79 53.84,31.78 54.17,31.45 54.45,31.45 54.65,31.25 54.71,31.3 Q1.1 54.73,31.3 54.09,30.66 55.81,30.73 55.81,30.61 C3.2
N$3
  Top 0.254: IC1.35 39.77,42.31 39.37,41.91 39.1,41.91 Q2.1 39.08,41.9 | 39.08,41.9 39.09,41.92 | C5.2 37.96,41.81 38.05,41.9 39.07,41.9 39.08,41.9
N$4
  Top 0.254: C44.2 21.15,9.37 21.34,8.96 20.86,8.48 20.86,8.44 19.65,8.44 19.64,8.43 IC9.16
N$5
  Top 0.254: 43.07,68.27 SV2.3 42.8,68.27 42.82,68.26 43.86,69.3 43.86,69.31 43.92,69.37 43.93,69.37 43.97,69.41 43.98,69.41 44.05,69.47 48.47,69.47 49.1,68.84 49.1,67.93 50.08,66.95 55.16,66.95 55.22,66.88 56.48,65.63 56.48,62.03 56.16,61.74 56.16,58.93 57.08,57.99 58.49,57.99 R2.S | R2.S
N$7
  Top 0.254: SV1.39 71.32,62.43 | 71.32,62.43 71.33,62.43 | 71.32,62.43 71.32,62.44 | R12.2 71.16,62.59 71.32,62.43
N$8
  Bottom 0.254: R16.2 14.15,29.93 14.15,29.41 14.05,29.41 C17.2 14.79,30.22 IC2.3
N$9  (via drill 0.6)
  Top 0.254: IC1.12 v48.63,52.85
  Bottom 0.254: v48.63,52.85 48.68,52.77 50.85,54.93 53.52,54.92 53.54,54.9 C1.+
N$10
  Bottom 0.254: IC2.46 20.46,26.05 17.91,23.61 16.06,23.61 16.01,23.56 R17.2
N$11
  Top 0.254: R2.E 58.53,55.85 62.59,59.91 63.73,59.91 R1.1 | R1.1 63.77,59.87 | R1.1
N$12
  Bottom 0.254: 49.34,4.8 49.37,4.77 | 49.34,4.8 R5.2 49.32,4.83 49.33,4.83 49.34,4.82 R45.2 | BU1.L2 49.63,5.02 49.57,4.96 49.33,4.81 49.34,4.8
N$13
  Bottom 0.254: U1.24 40.82,13.36 40,12.54 37.91,12.54 | Q3.2 37.49,12.39 37.54,12.44 37.91,12.54 | 37.91,12.54 37.91,12.49 37.83,12.57 | 37.51,12.41 | Q3.2 37.51,12.41 | 37.51,12.41 35.95,12.76 | C7.1 32.8,14.31 34.59,12.53 35.7,12.53 35.72,12.54 35.74,12.52 Q3.2
N$14
  Bottom 0.254: U1.23 41.49,14.68 43.51,12.53 45.38,12.53 45.41,12.5 45.42,12.52 Q3.1 45.48,12.52 45.58,12.62 46.57,12.53 47.36,11.83 C6.1
N$15
  Bottom 0.254: R11.1 45.59,27.77 45.62,27.65 44.09,26.12 44.09,24.9 44.1,24.88 U1.10 | R11.1 45.55,28.01 45.53,28.02 | 41.67,29.85 43.18,28.34 45.06,28.34 45.48,27.92 | 41.67,29.85 41.37,30.15 | 45.48,27.92 45.57,27.83 | R11.1 45.48,27.92 | 41.67,29.85 41.66,29.84 41.56,29.94 C8.1
N$16
  Bottom 0.254: U1.14 46.7,24.87 46.71,24.88 46.93,24.95 46.93,24.96 46.83,25.06 R4.2
N$17
  Bottom 0.254: U1.1 38.24,24.89 38.26,24.91 38.24,24.92 38.24,25.94 38.86,26.55 38.86,26.6 38.85,26.6 38.87,26.62 C11.1
N$18
  Bottom 0.254: BU1.L4 59.67,6.94 58.06,5.33 | R6.2 57.6,4.87 58.06,5.33 | 58.06,5.33 | R46.2 58.97,4.43 58.06,5.33
N$19
  Bottom 0.254: C19.1 28.6,39.79 26.74,41.66 Q4.2 26.82,41.72 26.81,41.71 26.79,41.74 24.63,41.74 24.42,41.53 | IC2.18 21.98,39.09 24.42,41.53 | 24.42,41.53 24.46,41.48 | 24.42,41.53 | R19.2 21.71,44.24 24.42,41.53
N$20
  Bottom 0.254: 17.2,41.78 Q4.1 | 17.2,41.78 17.16,41.81 | IC2.17 21.48,37.28 21.48,37.43 21.48,39.44 19.47,41.42 | 17.2,41.78 19.12,41.78 19.47,41.42 | R19.1 20.56,46.98 20.32,46.74 20.32,42.27 19.47,41.42
  Bottom 0.406: Q4.1 17.17,41.8 17.14,41.83 14.76,41.83 13.74,42.85 C18.1
N$21
  Bottom 0.406: Q5.3 69.52,64.75 69.57,64.8 69.09,65.14 R27.1
N$22
  Bottom 0.254: R18.2 22.06,23.88 22.95,24.77 23.59,24.77 23.99,25.18 23.98,27.79 23.97,27.81 23.98,27.81 IC2.39
N$23
  Top 0.254: 69.69,64.09 69.29,64.6 69.3,64.13 LED1.C 69.3,64.98 70.91,66.58 R12.1
N$24
  Top 0.254: JP2.3 6.07,51 6.4,50.67 R22.2 8.42,50.64 8.55,50.77 8.54,50.78 C26.2 8.92,50.78 10.54,49.15 11.15,49.15 11.18,49.13 | 11.18,49.13 11.19,49.12 | 11.18,49.13 R21.1 11.42,49.13 12.07,49.78 12.07,49.95 12.64,50.52 IC5.19
N$25
  Bottom 0.254: R34.1 28.57,34.72 IC2.25
N$26
  Bottom 0.254: IC11.2 5.54,37.61 4.93,37 3.34,37 2.8,37.55 2.8,39.01 2.72,39.08 2.77,39.13 JP6.1
N$27
  Bottom 0.254: IC4.4 71.86,64.96 70.44,63.52 70.45,62.17 70.4,62.12 70.46,62.06 Q5.1
N$28
  Bottom 0.254: R17.1 14.2,23.55 14.19,23.54 14.16,23.56 C21.1
N$29
  Bottom 0.254: IC2.44 21.48,26.89 21,26.41 21,25.13 20.07,24.2 20.07,23.48 20.13,23.41 20.09,23.37 C20.1
N$30
  Bottom 0.254: R20.1 28.63,30.98 28.6,30.96 28.34,31.22 IC2.32
N$31
  Bottom 0.254: R18.1 21.76,22.37 17.36,22.37 16.58,21.58 11.95,21.6 11.74,21.38 11.75,21.37 C22.1
N$32  (via drill 0.5)
  Top 0.254: IC9.11 18.29,4.52 17.57,3.8 17.44,3.8 v17.43,3.79 | v16.28,15.97 18.18,15.97 v18.38,16.17 | v31.83,26.23 32.63,27.03 32.63,29.94 35.98,33.33 v35.98,34.57 | IC8.4 33.02,37.88 31.87,37.88 v31.82,37.93
  Bottom 0.254: v17.43,3.79 17.43,3.94 17.16,4.2 17.16,4.74 16.26,5.7 16.25,11.42 16.64,11.82 16.64,15.65 v16.28,15.97 | v18.38,16.17 21.05,16.17 23.17,18.29 30.71,18.29 32.6,20.19 32.6,24.59 31.83,25.37 v31.83,26.23 | v35.98,34.57 35.97,34.56 32.6,37.93 v31.82,37.93
N$33
  Top 0.254: R21.2 11.1,50.83 11.12,50.82 11.32,51.02 IC5.18
N$34
  Top 0.254: R23.2 11.22,52.7 12.39,51.52 IC5.17
N$35
  Top 0.254: JP2.2 3.18,53.54 3.24,53.6 3.89,52.96 C29.1 8.62,52.96 8.74,52.84 8.82,52.91 R24.2 9.17,52.94 10.63,54.4 R23.1 11.84,54.4 12.54,53.7 12.54,52.18 12.69,52.02 13.45,52.02 IC5.16
N$36
  Top 0.254: IC5.14 14.34,53.37 14.35,53.36 14.35,52.79 14.56,52.58 17.34,52.58 17.61,52.01 IC5.6 18.28,52.02 18.3,52 18.34,52.04 19.27,52.04 19.94,52.71 C38.2
N$37
  Bottom 0.254: 24.61,12.16 24.58,12.2 R36.2 | 24.61,12.16 C48.2 | 24.61,12.16 24.65,12.12
N$38
  Top 0.254: C36.1 17.32,57.8 16.84,57.32 IC5.9
N$39  (via drill 0.6)
  Top 0.254: v39.2,59.95 39.27,59.95 39.27,58.25
  Top 0.61: v39.2,59.95 39.2,59.84 38.89,59.53 L3.P$1
  Bottom 0.254: IC3.9 37.36,62.37 37.29,62.3 37.28,61.46 38.79,59.95 v39.2,59.95
N$40
  Top 0.254: C36.2 15.32,57.77 15.84,57.24 IC5.11
N$41
  Bottom 0.254: R37.2 C49.2
N$43
  Top 0.406: IC7.8 32.83,65.68
  Top 0.61: L2.P$2 17.47,71.49
  Top 1.016: 17.47,71.49 17.47,71.32 21.15,67.65 25.28,67.65 25.29,67.63 C32.2 24.68,67.51 24.81,67.63 30.67,67.63 32.81,67.63 | 33.35,70.32 33.35,70.31 | 33.35,70.32 D1.C | IC7.8 32.81,65.68 32.81,67.63 | 33.35,70.32 32.81,69.78 32.81,67.63
N$44
  Top 0.406: 27.68,65.65 27.69,65.66 | 27.68,65.65 IC7.1 | C32.1 24.68,65.37 24.95,65.64 27.65,65.63 27.68,65.65
N$46  (via drill 0.5)
  Top 0.254: R29.2 27.55,60.01 28.68,58.88 v28.68,58.31 28.68,58.21
  Top 0.406: v28.68,58.31 v28.68,58.32 | 28.68,58.21 v28.68,58.32 | v28.68,58.32 28.67,58.34
  Top 0.61: R29.2 27.55,61.82 27.58,61.84 IC7.4 25.14,61.84 25.06,61.92 R28.1
  Bottom 0.254: R47.2 v28.68,58.31
N$47  (via drill 0.6)
  Top 0.254: C34.1 34.75,61.78 34.73,61.8 32.85,61.8 32.81,61.84 | 32.81,61.84 32.78,61.87 | IC7.5 32.81,61.84
  Top 0.406: IC7.5 32.78,61.84 32.77,61.83
  Top 0.61: 30.19,64.74 30.19,64.65 30.19,64.5 30.24,64.45 30.31,64.38 IC7.7 | 31.66,61.84 32.78,61.84 | 30.18,62.39 30.72,61.84 31.66,61.84 | 31.66,61.84 31.66,58.72 30.51,57.57 30.66,57.26 30.47,57.14 30.61,56.91 C46.+
  Top 0.813: 30.24,64.45 30.27,64.48 | 30.24,64.45 | 30.18,62.39 30.18,64.39 30.24,64.45 | 30.19,64.65 30.18,64.65 30.18,65.84 v30.17,65.85
  Bottom 0.406: D2.C 33.27,70.48 34.36,71.57
  Bottom 0.61: C47.1 33.53,71.28 33.32,71.06 33.32,70.57 33.33,70.55 33.27,70.49 D2.C
  Bottom 0.813: 33.16,68.46 30.56,65.85 v30.17,65.85
  Bottom 1.016: D2.C 33.18,70.52 33.16,70.52 33.16,68.46
N$48
  Top 0.254: IC5.27 16.84,47.27 17.17,46.93 20.91,46.93 20.95,46.89 20.95,46.9 C57.1
N$49
  Top 0.254: IC9.2 14.12,8.93 13.94,8.74 13.66,8.69 13.67,8.7 C40.2 C39.1
N$50
  Top 0.254: C40.1 11.92,8.78 11.96,8.82 11.96,9.87 | 11.96,9.87 L4.1 | 11.96,9.87 11.98,9.87 11.95,9.85
  Top 0.61: 11.95,9.85 11.95,9.78 11.93,9.76 10.2,9.76 | X3.1 4.13,9.59 4.3,9.76 10.2,9.76 | 10.2,9.76 D3.1
N$51
  Top 0.254: R30.1 13.66,2.38 13.91,2.63 C41.1 14.21,4.74 15.65,6.18 IC9.7
N$52
  Top 0.254: C45.2 21.06,7.49 20.62,7.93 19.65,7.93 IC9.15
N$53  (via drill 0.5)
  Top 0.254: v24.87,9.37 C44.1
  Bottom 0.254: R25.1 26.36,9.3 26.29,9.37 v24.87,9.37 24.87,9.4 24.86,9.42 24.64,9.2 22.32,9.2 22.1,9.42 IC12.3
N$54  (via drill 0.5)
  Top 0.254: v23.61,6.01 23.65,7.27 C45.1 v25.12,7.49
  Bottom 0.254: IC12.5 23.32,6.01 v23.61,6.01 | 26.53,7.49 R26.1 | v25.12,7.49 26.53,7.49 | 26.53,7.49 26.56,7.51
N$55
  Bottom 0.254: 30.45,28.27 30.51,28.21 | 30.45,28.27 R13.1 | 30.45,28.27 29.51,29.22 IC2.36 25.2,29.24 25.2,29.6 25.2,30.23 IC2.34 IC2.33
N$56
  Bottom 0.254: IC2.10 18.13,33.74 18.11,33.75 | IC2.10 IC2.9 | IC2.11 18.1,34.19 18.13,34.17 IC2.10 | 18.13,34.73 IC2.12 | IC2.11 18.13,34.73 | 18.13,34.73 18.14,34.74 | IC2.11 18.1,34.18 18.06,34.22 18.06,35.21 16.16,37.11 R14.1
N$57
  Bottom 0.254: R35.2 20.97,12.22 20.98,12.24 21.02,12.2 21.43,12.2 | 21.43,12.2 R36.1 | 21.43,12.2 21.43,12.15 21.45,12.13 IC12.2
N$58
  Bottom 0.254: IC12.1 20.6,10.23 19.37,11.46 19.37,12.06 R35.1 19.02,12.22 17.59,13.65 17.59,20.02 17.42,20.2 17.47,20.25 C50.2
N$59
  Bottom 0.254: R38.2 21,3.32 21.01,3.31 R37.1 22.14,3.31 22.13,3.32 22.13,5.16 22.1,5.19 22.1,5.95 22.09,5.96 22.1,5.97 IC12.6
N$60
  Bottom 0.254: IC12.7 21.45,4.86 21.1,4.51 19.82,4.51 | 19.82,4.51 19.69,4.51 19.27,4.09 19.27,3.45 19.23,3.41 19.24,3.4 R38.1 | 19.82,4.51 19.68,4.51 16.75,7.24 16.75,11.03 17.12,11.4 17.11,18.17 16.62,18.66 13.47,18.66 | 13.47,18.66 C51.2 | 13.47,18.66 13.43,18.7
N$61
  Bottom 0.254: IC11.4 5.31,38.91 3.6,40.62 3.6,40.82 2.8,41.62 JP6.2
N$63  (via drill 0.5)
  Top 0.254: v4.64,37.94 4.64,43.3 3.72,44.21 2.82,44.21 2.81,44.23 JP6.3
  Bottom 0.254: IC11.3 4.96,38.26 v4.64,37.94
N$64
  Bottom 0.254: IC11.5 5.65,39.56 5.06,40.15 5.06,44.54 2.81,46.79 2.8,46.78 JP6.4
N$67
  Top 0.254: C58.1 21,50.03 20.99,50.02 IC5.2
N$68  (via drill 0.8)
  other vias: 15.84,51.02
N$69
  Bottom 0.254: R4.1 50.42,25.03 50.44,25.01 50.29,24.87 R15.2
PGC  (via drill 0.5)
  Top 0.254: IC1.52 50.13,35.96 50.38,35.7 50.38,35.57 v50.47,35.48 | SV3.5 39.67,54.17 39.67,50.68 39.56,50.68 v39.36,50.48 | v41.75,33.05 41.65,33.05 41.08,33.85 v41.08,37.95
  Bottom 0.254: v50.47,35.48 49.27,35.46 48.78,35.02 48.78,34.7 47.12,33.08 44.48,33.06 v41.75,33.05 | v39.36,50.48 39.36,50.42 39.35,49.94 40.24,49.04 41.48,47.78 41.48,43.3 41.49,39.93 41.08,39.52 v41.08,37.95
PGD  (via drill 0.5)
  Top 0.254: IC1.47 47.63,35.97 47.13,35.48 47.16,35.06 v46.83,34.73 | SV3.4 41.07,55.25 40.38,54.58 40.38,50.78 v40.67,50.49 | v42.59,34.12 41.95,34.12 41.52,34.52 41.53,36.84 41.53,37.18 42,37.65 v41.99,38.94
  Bottom 0.254: v42.59,34.12 42.64,34.12 43.23,34.71 v46.83,34.73 | v40.67,50.49 42,49.14 42,46.82 42.02,43.5 v41.99,38.94
PWMOUT
  Bottom 0.254: 66.37,66.76 66.35,66.76 66.36,66.77 R27.2
  Bottom 0.406: SV2.20 63.11,70.71 66.37,67.44 66.37,66.76 66.37,66.63 66.4,66.6 66.37,66.58
RA0
  Top 0.254: IC1.30 36.35,44.8 35.7,45.5 32.27,45.5 30.85,44.07 30.12,44.07 30.1,44.06 30.08,44.09 JP1.4
RA1
  Top 0.254: JP1.3 31.14,46.63 31.82,45.95 35.96,45.95 36.59,45.31 42.75,45.31 42.76,45.3 IC1.29
RA2
  Top 0.254: JP1.2 31.17,48 35.7,48 37.89,45.81 42.78,45.81 IC1.28
RA3
  Top 0.254: JP1.1 31.33,51.71 32.24,50.81 37.87,50.81 39.09,49.59 40.96,49.59 41.67,50.3 41.67,50.31 42.51,51.15 IC1.20
ROTEN0  (via drill 0.5)
  Top 0.254: v38.64,48.21 41.13,48.21 41.68,48.77 41.68,48.76 41.72,48.8 IC1.22
  Bottom 0.254: 34.34,46.91 36.73,44.52 | 37.72,44.74 38.09,45.13 38.1,45.99 39.09,46.97 39.09,47.92 v38.64,48.21
  Bottom 0.305: JP5.2 34.34,46.91 | 36.73,44.52 R33.1 37.72,44.74
ROTEN1  (via drill 0.5)
  Top 0.254: v38.17,49.29 38.23,49.29 38.43,49.09 41.18,49.09 41.38,49.29 42.68,49.29 42.7,49.32 42.72,49.3 IC1.21
  Bottom 0.254: JP5.3 37.04,49.51 | R32.1 37.91,49.55 v38.17,49.29
  Bottom 0.305: 37.11,49.59 37.13,49.6 | 37.11,49.59 R32.1 | 37.04,49.51 37.11,49.59
ROTEN2  (via drill 0.5)
  Top 0.254: v43.17,52.72 44.89,52.72 45.14,52.47 45.14,51.16 IC1.19 | IC1.19 | IC1.19
  Bottom 0.254: R31.1 44.47,52.74 44,52.33 43.16,52.43 | JP5.4 34.34,52.09 34.97,52.62 41.46,52.61 41.63,52.43 43.16,52.43 | 43.16,52.43 v43.17,52.72
RX0
  Bottom 0.254: R10.1 61.19,19.64 60.24,18.69 59.77,18.69 | 59.77,18.69 59.76,18.69 59.54,18.91 R9.1 57.77,20.87 BU1.5 | 59.77,18.69 C10.1
SCLK  (via drill 0.5)
  Top 0.254: IC1.58 53.13,39.73 52.85,40.01 51.29,40.01 49.03,41.19 46.37,41.19 46.29,41.1 46.17,40.98 v46.17,39.6
  Bottom 0.254: IC2.28 38.19,33.23 44.57,39.6 v46.17,39.6
SI  (via drill 0.5)
  Top 0.254: IC1.57 52.63,39.38 52.45,39.55 51.01,39.55 48.83,40.65 47.4,40.65 v47.11,40.34
  Bottom 0.254: IC2.29 38.52,32.72 40.5,34.7 | v47.11,40.34 47.07,40.34 47.07,39.88 47.06,39.11 45.94,38.02 43.84,38 40.5,34.7 | 40.5,34.7 40.52,34.71
SI_L  (via drill 0.5)
  Top 0.254: v13.94,20.63 12.37,20.63 10.32,18.57 9.59,18.57 4.74,23.42 4.77,31.74 4.77,33.17 11,39.4 11.45,39.86 11.45,44.44 12.28,45.28 | IC5.26 16.34,46.17 15.73,45.55 12.55,45.55 12.28,45.28 | 12.28,45.28 12.3,45.29
  Bottom 0.254: C50.1 14.32,20.25 v13.94,20.63
SI_R  (via drill 0.5)
  Top 0.254: v9.88,19.67 9.35,19.67 5.31,23.7 5.34,31.48 5.34,32.94 5.59,33.19 11.93,39.52 11.93,43.83 13.17,45.08 18.34,45.08 18.52,45.26 19.24,45.97 v19.36,45.97 | IC5.1 19.27,49.52 v19.65,49.14
  Bottom 0.254: C51.1 10.89,18.66 v9.88,19.67 | v19.65,49.14 19.64,46.25 v19.36,45.97
SI_RCLK
  Top 0.254: IC1.36 40.48,41.8 39.08,40.4 39.08,39.52 39.11,39.49 39.08,39.46 Q2.2 | Q2.2 37.91,39.34 37.89,39.31 37.76,39.31 C4.2 37.65,39.2 37.63,39.19 37.65,39.17 | IC8.2 35.66,36.31 35.64,36.33 | IC8.1 IC8.2 | IC8.2 35.96,36.82 37.4,36.82 39.13,38.56 39.13,39.27 39.12,39.29 39.13,39.29 Q2.2
SI_VDD
  Top 0.254: C28.1 19.88,12.18 19.97,12.1 19.96,12.08 19.96,11.4 19.97,9.43 IC9.18 18.96,9.43 18.84,9.43 18.84,6.95 | IC9.13 19.52,6.93 19.49,6.89 19.42,6.95 18.84,6.95 | 18.84,6.95 18.85,6.94 18.79,6.88 | 18.79,6.88 IC9.12 18.81,6.18 20.19,4.8 C23.1 | IC9.8 16.79,6.82 16.79,6.83 16.79,6.88 18.79,6.88
  Top 0.305: 20.2,2.99 20.21,2.98 | 20.2,2.99 L5.1 | C23.1 20.19,3 20.2,2.99
SO  (via drill 0.5)
  Top 0.254: IC1.56 52.13,39.04 52.09,39.08 48.89,39.08 48.39,39.57 48.37,39.57 v48.14,39.79
  Bottom 0.254: IC2.30 29.39,32.22 29.56,32.23 38.88,32.23 40.64,34 43.98,37.25 46.89,37.27 48.12,38.52 v48.14,39.79
SPI_SCK  (via drill 0.6)
  Top 0.254: 44.06,35.08 44.06,35.07 | 44.06,35.08 44.06,36 44.34,36.28 45.83,36.26 46.13,36.57 IC1.44 | 44.06,35.08 44.05,32.01 45.53,30.49 45.49,22.81 44.69,21.99 43.97,21.99 v43.77,22.19 43.77,22.22 43.34,22.65 41.88,22.65 41.52,22.29 39.84,22.29 39.46,22.66 21.43,22.66 18.65,25.44 18.65,31.25 19.08,30.85 19.06,30.87 CON1.5
  Bottom 0.254: v43.77,22.19 43.75,22.19 42.8,23.14 42.8,24.99 42.79,24.97 U1.8
SPI_SDI  (via drill 0.6)
  Top 0.254: IC1.45 | IC1.45 | IC1.45 46.61,36.84 46.61,36.33 46.03,35.76 44.86,35.76 44.57,35.51 44.57,35.18 44.59,32.25 46.12,30.76 46.1,22.56 44.85,21.35 42.84,21.35 v42.45,21.75 42.4,21.75 42.35,21.7 39.65,21.7 39.16,22.19 21.2,22.19 14.25,29.11 14.25,30.8 14.28,30.83 14.24,30.87 CON1.7
  Bottom 0.254: v42.45,21.75 42.42,21.75 42.14,22.21 42.14,24.76 42.18,24.8 42.14,24.84 U1.7
SPI_SDO  (via drill 0.6)
  Top 0.254: v41.49,20.82 41.51,20.81 45.09,20.81 46.74,22.46 46.75,30.85 45.69,31.93 45.11,32.5 45.11,34.98 45.22,35.08 46.05,35.08 47.13,36.16 IC1.46 | v40.2,23.13 32.74,23.13 26.56,29.32 26.56,30.88 26.57,30.89 | 26.57,30.89 26.58,30.9 | 26.57,30.89 CON1.2
  Bottom 0.254: U1.6 41.49,24.84 41.43,24.78 41.49,24.72 41.49,23.17 | 41.49,23.17 v41.49,20.82 | v40.2,23.13 40.22,23.16 41.49,23.17
SW1
  Top 0.254: 58.82,40.58 | 58.82,40.58 S1.3 | IC1.63 58.6,40.8 58.82,40.58
SW2
  Top 0.254: JP3.2 59.33,27.39 59.34,27.37 59.31,27.35 55.77,27.34 53.48,29.56 53.48,34.49 52.94,35.01 51.86,36.07 51.13,36.8 IC1.54
TPIN+  (via drill 0.6)
  Top 0.254: v57.76,15.82 57.76,18.28 55.43,20.72 55.43,24.31 | 55.43,24.31 55.13,24.5 BU1.4 | 55.43,24.31 55.16,24.53
  Bottom 0.254: U1.13 46.04,25.97 46.23,26.14 54.58,26.14 55.12,25.57 55.12,24.53 55.13,24.52 BU1.4 | R9.2 v57.77,15.82 v57.76,15.82
TPIN-
  Bottom 0.254: U1.12 45.39,26.07 45.94,26.65 57.19,26.64 57.65,26.18 57.65,24.62 57.67,24.59 BU1.6 57.67,24.48 57.65,24.45 58.41,23.69 59.17,23.69 61.22,21.65 R10.2
TPOUT+  (via drill 0.6)
  Top 0.254: 51.59,21.62 51.32,21.96 | BU1.1 51.59,21.62 | 48.25,18.05 48.25,18.2 51.59,21.62
  Top 0.406: v47.93,17.99 47.93,17.96 48.02,18.05 48.25,18.05
  Bottom 0.254: BU1.1 48.24,21.96 45.38,19.09 45.38,17.77 45.39,17.77 U1.17 | R7.2 48.31,18.55 v47.93,17.99
TPOUT-
  Bottom 0.254: 53.85,21.12 53.06,20.34 47.49,20.34 46.05,18.9 46.05,17.66 46.04,17.64 U1.16 | 53.85,21.12 53.86,21.14 53.86,21.58 54.17,21.89 BU1.3 | 53.85,21.12 53.84,21.13 | 53.85,21.12 | R8.2 54.83,20.13 53.85,21.12
TX0  (via drill 0.6)
  Top 0.254: BU1.2 52.88,18.13 v51.62,16.93
  Bottom 0.254: 53.2,18.57 53.24,18.52 | 53.2,18.57 R8.1 | R7.1 53.2,18.57 | R8.1 53.12,18.57 53.1,18.55 53.2,18.45 | 53.17,18.57 53.18,18.57 | R8.1 53.17,18.57 | 53.17,18.57 51.62,17.09 v51.62,16.93 51.64,16.96 | 55.01,14.77 55.11,14.66 55.37,14.4 | R8.1 53.13,18.58 53.11,18.6 | 55.01,14.77 54.99,14.75 55.54,14.2 L6.1 | 55.01,14.77 55.01,14.92 53.36,16.57 C9.1 53.36,18.26 53.13,18.49 R8.1
V+
  Top 0.61: X2.1 8.22,70.36 9.2,69.39 PAD1.1
  Bottom 1.016: D2.A 25.72,70.34 X2.1
VB1
  Bottom 0.254: R44.2 28.08,9.17 28.01,9.25 28.05,9.29 R25.2 28.06,9.21 28.16,9.31 28.16,10.97 28.24,11.04 | 28.24,11.04 R43.1 | 28.24,11.04 C53.2
VB2
  Bottom 0.254: C54.2 28.03,5.52 28.06,5.49 R41.1 28.1,5.53 28.08,5.54 28.18,5.64 28.18,7.4 | 28.18,7.4 28.17,7.38 | 28.18,7.4 R26.2 | R42.1 28.24,7.45 28.18,7.4
VDD_2,5
  Bottom 0.254: IC2.31 25.45,31.72 24.97,32.21 | 24.97,32.21 24.97,33.1 | 24.97,33.1 IC2.24 24.98,36.1 25.01,36.14 25.66,36.14 26.37,36.85 C37.1 | 21.28,32.22 20.94,32.22 20.87,32.29 20.07,32.29 19.99,32.21 IC2.7 16.99,32.22 16.87,32.34 16.87,33.47 16.86,33.48 12.26,33.48 12.25,33.47 C55.1 11.67,33.5 11.66,33.51 11.46,33.31 IC6.5 | 21.28,32.22 21.28,30.66 20.03,30.66 19.5,31.22 IC2.5 | 24.97,32.21 24.95,32.21 24.94,32.22 23.49,32.24 23.21,31.96 22.09,31.95 21.82,32.22 21.28,32.22 | 24.97,33.1 24.96,33.1
VEE
  Top 0.254: R2.A | R2.A | R2.A 59.26,61.32 59.26,69.4 60.57,70.71 60.57,70.76 60.56,70.77 60.57,70.78 SV2.18
VREF  (via drill 0.5)
  Top 0.254: IC1.27 41.14,46.3 v40.66,46.79
  Bottom 0.254: v40.66,46.79 40.66,46.78 40.5,46.62 VR1.1 40.51,43.52 40.55,43.48 40.5,43.43 40.5,41.47 39.61,40.58 37.74,40.58 36.72,41.6 35.12,41.6 34.64,41.12 R48.1
VS_L  (via drill 0.5)
  Top 0.254: v8.51,23.56 7.14,23.56 6.4,24.3 6.43,30.78 6.43,32.26 6.84,32.67 13.02,38.8 13.02,42.98 13.85,43.81 v14.46,43.81 | IC5.25 15.84,47.66 15.83,46.94 15.32,46.4 v15.31,46.41
  Bottom 0.254: v8.51,23.56 C21.2 | v14.46,43.81 14.47,44.95 15.31,45.79 v15.31,46.41
VS_R  (via drill 0.5)
  Top 0.254: v8.53,22.29 7.6,22.29 5.85,24.05 5.87,31.15 5.87,32.5 6.46,33.09 12.46,39.05 12.46,43.5 13.1,44.14 | v17.38,43.67 16.49,44.57 13.53,44.58 13.53,44.57 13.1,44.14 | v18,47.72 17.54,47.72 17.35,47.91 17.35,48.54 17.33,48.57 17.34,48.58 IC5.28 | 13.1,44.14 13.11,44.15
  Bottom 0.254: C22.2 9.45,21.37 v8.53,22.29 | v17.38,43.67 17.38,47.08 v18,47.72
VUSB  (via drill 0.6)
  Top 0.254: v50.69,32.67 50.71,32.7 50.71,31.6 50.83,31.49 50.84,24.71 49.22,23.11 49.22,22.03 41,13.92 41,10.09 41.52,9.54 X1.VBUS 41.52,8.81 40.96,8.25 v38.09,8.25 | IC1.13 48.13,48.53 v48.54,48.13
  Bottom 0.254: 50.68,32.89 v50.69,32.67 50.68,32.64 52.86,32.67 53.38,33.2 53.39,34.21 53.11,34.51 53.11,35.62 52.11,36.62 51.35,37.37 50.61,38.07 50.57,46.46 48.91,48.13 v48.54,48.13 | v38.09,8.25 36.33,8.25 36.29,8.29 36.25,8.24 36.2,8.24 36.17,8.22 | 36.17,8.22 36.16,8.21 | C16.1 36.17,8.22
WPSD  (via drill 0.5)
  Top 0.254: IC1.38 40.95,40.8 40.61,40.45 40.61,38.61 36.88,34.92 36.87,34.52 36.88,33.69 36.88,33.08 33.13,29.34 v33.14,25.46 | v19.87,14.19 16.2,14.19 v14.77,12.77 | CON1.12 8.39,2.87 8.39,2.88 8.41,2.9 v8.41,5.43
  Bottom 0.254: v33.14,25.46 33.14,19.98 30.9,17.75 23.42,17.75 v19.87,14.19 | v14.77,12.77 14.77,11.56 14.76,5.83 14.76,5.8 14.37,5.43 v8.41,5.43
XCS  (via drill 0.5)
  Top 0.254: v23.28,34.47 23.31,34.47 23.87,35.03 33.57,35.03 34.1,35.58 34.1,38.66 33.66,39.11 33.66,42.84 34.22,43.4 35.73,43.44 35.84,43.55 39.72,43.54 39.97,43.3 IC1.33
  Bottom 0.254: IC2.23 24.48,35.06 24.01,34.59 23.4,34.59 v23.28,34.47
